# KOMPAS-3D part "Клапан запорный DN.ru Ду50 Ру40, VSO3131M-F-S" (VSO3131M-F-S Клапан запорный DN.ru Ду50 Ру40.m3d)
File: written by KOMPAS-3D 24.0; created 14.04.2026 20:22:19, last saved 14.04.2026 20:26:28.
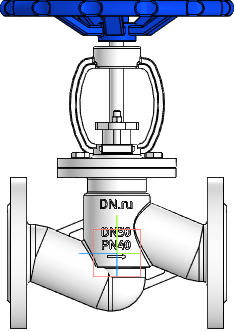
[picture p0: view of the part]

Document properties: Автор: R2D2; Полное имя файла: VSO3131M-F-S Клапан запорный DN.ru Ду50 Ру40.cdw

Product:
- Part/product: Клапан запорный DN.ru Ду50 Ру40  | designation VSO3131M-F-S
    Масса: 11.97
    Раздел спецификации: Прочие изделия
    Форматы листов документа: A2
    Примечание: D090-02142

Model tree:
1. Операция без истории:3

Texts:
  VSO3131M-F-S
